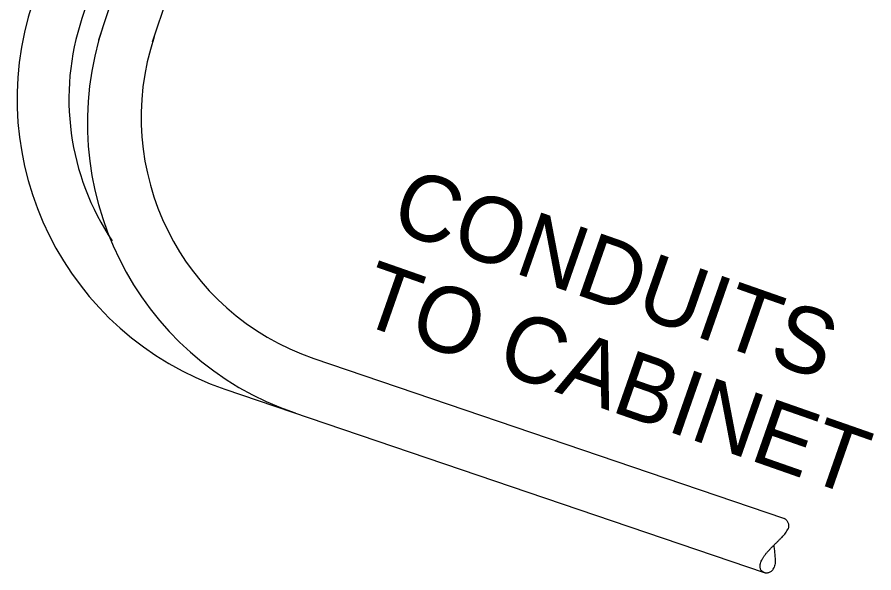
# Model space of a CAD drawing. Extents: x 99862 to 103151, y 100000 to 105076.
# Drawn here: x 102768 to 102976.3, y 103903.7 to 104038.7 of the extents above; entities that cross this region are included whole.
import ezdxf

# ---------------------------------------------------------------- set-up
doc = ezdxf.new("R2010")
doc.units = 0
for name, color, linetype in [('Level 1', 7, 'Continuous'), ('Level 18', 7, 'Continuous'), ('Level 20', 7, 'Continuous')]:
    doc.layers.add(name, color=color, linetype=linetype)

msp = doc.modelspace()

# ---------------------------------------------------------------- linework, layer by layer
at = {"layer": 'Level 1'}
msp.add_line((102951.95, 103910.4), (102951.95, 103910.4), dxfattribs=at)
for points, degree in [([(102954.3, 103916.99), (102954.34, 103916.97), (102954.47, 103916.93), (102954.67, 103916.82), (102954.9, 103916.64), (102955.11, 103916.41), (102955.29, 103916.14), (102955.43, 103915.8), (102955.53, 103915.41), (102955.54, 103914.95), (102955.46, 103914.61), (102955.39, 103914.42)], 3), ([(102949.59, 103903.81), (102949.54, 103903.82), (102949.4, 103903.88), (102949.2, 103904), (102948.98, 103904.19), (102948.81, 103904.42), (102948.67, 103904.72), (102948.58, 103905.08), (102948.58, 103905.51), (102948.67, 103905.99), (102948.86, 103906.53), (102949.14, 103907.1), (102949.5, 103907.66), (102949.9, 103908.19), (102950.33, 103908.71), (102950.77, 103909.2), (102951.22, 103909.68), (102951.68, 103910.14), (102952.14, 103910.6), (102952.6, 103911.04), (102953.05, 103911.49), (102953.51, 103911.94), (102953.95, 103912.4), (102954.38, 103912.87), (102954.79, 103913.35), (102955.15, 103913.87), (102955.33, 103914.24), (102955.39, 103914.42)], 3), ([(102951.94, 103910.4), (102951.94, 103910.4), (102951.94, 103910.4), (102951.94, 103910.4)], 2), ([(102951.94, 103910.4), (102951.95, 103910.3), (102951.98, 103909.99), (102952.04, 103909.48), (102952.11, 103908.85), (102952.17, 103908.21), (102952.23, 103907.57), (102952.26, 103906.94), (102952.27, 103906.3), (102952.22, 103905.67), (102952.12, 103905.28), (102952.06, 103905.1)], 3), ([(102949.59, 103903.81), (102949.62, 103903.79), (102949.75, 103903.75), (102949.98, 103903.7), (102950.27, 103903.7), (102950.57, 103903.74), (102950.89, 103903.83), (102951.21, 103904), (102951.53, 103904.24), (102951.83, 103904.59), (102952, 103904.9), (102952.06, 103905.09)], 3)]:
    msp.add_open_spline(points, degree=degree, dxfattribs=at)
at = {"layer": 'Level 18'}
for p, q in [((102823.87, 104158.85), (102783.79, 104038.37)), ((102828.93, 104156.82), (102787.78, 104033.12)), ((102840.92, 104152.99), (102800.86, 104032.57)), ((102840.16, 103955.77), (102954.3, 103916.99)), ((102818.55, 103948.33), (102949.59, 103903.81))]:
    msp.add_line(p, q, dxfattribs=at)
for centre, radius, end in [((102842.51, 104018.84), 74.47, 251.2333), ((102842.51, 104018.84), 61.88, 213.8934), ((102859.58, 104013.04), 74.47, 251.2333), ((102860.07, 104014.36), 61.88, 251.2333)]:
    msp.add_arc(centre, radius, 161.5999, end, dxfattribs=at)

# ---------------------------------------------------------------- texts
at = {"layer": 'Level 20'}
for s, p in [('CONDUITS', (102858.19, 103987.3)), ('TO CABINET', (102850.26, 103964.65))]:
    msp.add_text(s, height=16, rotation=340.7081, dxfattribs=at).set_placement(p)

doc.saveas('drawing.dxf')
